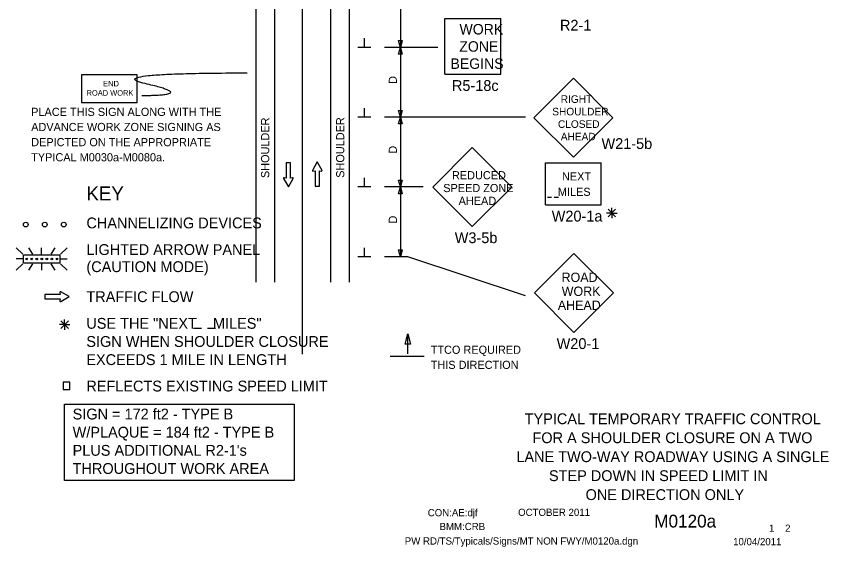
# Model space of a CAD drawing. Extents: x 16737 to 18470, y 7218 to 8193.
# Drawn here: x 16737 to 17435, y 7218 to 7674 of the extents above; entities that cross this region are included whole.
import ezdxf

# ---------------------------------------------------------------- set-up
doc = ezdxf.new("R2010")
doc.units = 0
for name, color, linetype in [('BORDER', 7, 'Continuous'), ('BORDER_SIGNAL_WO', 7, 'Continuous'), ('MT_SCRATCH_LEVEL_E', 7, 'Continuous'), ('PAVT_EDGE_EX', 7, 'Continuous'), ('TRAFFIC_SIGNS_PR', 7, 'Continuous'), ('TYPICAL_TEXT_DIMEN_EX', 7, 'Continuous'), ('TYPICAL_TEXT_DIMEN_PR', 7, 'Continuous')]:
    doc.layers.add(name, color=color, linetype=linetype)

msp = doc.modelspace()

# ---------------------------------------------------------------- linework, layer by layer
at = {"layer": 'MT_SCRATCH_LEVEL_E'}
for p, q in [((16972.86, 7548.17), (16969.12, 7548.17)), ((16969.12, 7548.17), (16969.12, 7534.91)), ((16972.86, 7548.17), (16969.12, 7548.17)), ((16969.12, 7548.17), (16969.12, 7534.91)), ((16972.86, 7534.91), (16972.86, 7548.17)), ((16972.86, 7534.91), (16972.86, 7548.17)), ((16995.75, 7548.82), (16991.64, 7541.58)), ((16995.75, 7548.82), (16991.64, 7541.58)), ((16999.89, 7541.58), (16995.75, 7548.82)), ((16999.89, 7541.58), (16995.75, 7548.82)), ((16992.12, 7540.9), (16993.9, 7541.21)), ((16992.12, 7540.9), (16993.9, 7541.21)), ((16993.9, 7541.21), (16993.9, 7527.96)), ((16993.9, 7541.21), (16993.9, 7527.96)), ((16997.64, 7527.96), (16997.64, 7541.21)), ((16997.64, 7541.21), (16999.42, 7540.9)), ((16997.64, 7527.96), (16997.64, 7541.21)), ((16997.64, 7541.21), (16999.42, 7540.9)), ((16966.86, 7534.54), (16971.01, 7527.3)), ((16966.86, 7534.54), (16971.01, 7527.3)), ((16969.12, 7534.91), (16967.34, 7535.22)), ((16969.12, 7534.91), (16967.34, 7535.22)), ((16971.01, 7527.3), (16975.12, 7534.54)), ((16971.01, 7527.3), (16975.12, 7534.54)), ((16974.64, 7535.22), (16972.86, 7534.91)), ((16974.64, 7535.22), (16972.86, 7534.91)), ((16993.9, 7527.96), (16997.64, 7527.96)), ((16993.9, 7527.96), (16997.64, 7527.96)), ((16775.11, 7434.93), (16761.85, 7434.93)), ((16761.85, 7434.93), (16761.85, 7431.19)), ((16775.11, 7434.93), (16761.85, 7434.93)), ((16761.85, 7434.93), (16761.85, 7431.19)), ((16761.85, 7431.19), (16775.11, 7431.19)), ((16761.85, 7431.19), (16775.11, 7431.19)), ((16774.79, 7436.71), (16775.11, 7434.93)), ((16774.79, 7436.71), (16775.11, 7434.93)), ((16775.11, 7431.19), (16774.79, 7429.41)), ((16775.11, 7431.19), (16774.79, 7429.41)), ((16782.72, 7433.08), (16775.48, 7437.19)), ((16782.72, 7433.08), (16775.48, 7437.19)), ((16775.48, 7428.94), (16782.72, 7433.08)), ((16775.48, 7428.94), (16782.72, 7433.08))]:
    msp.add_line(p, q, dxfattribs=at)
for centre, start, end in [((16992.04, 7541.36), 150.42484, 279.96381), ((16992.04, 7541.36), 150.42484, 279.96381), ((16999.48, 7541.36), 260.03619, 29.77312), ((16999.48, 7541.36), 260.03619, 29.77312), ((16967.27, 7534.76), 80.03619, 209.77312), ((16967.27, 7534.76), 80.03619, 209.77312), ((16974.71, 7534.76), 330.42484, 99.96381), ((16974.71, 7534.76), 330.42484, 99.96381), ((16775.25, 7436.79), 60.42484, 189.96381), ((16775.25, 7436.79), 60.42484, 189.96381), ((16775.25, 7429.34), 170.03619, 299.77312), ((16775.25, 7429.34), 170.03619, 299.77312)]:
    msp.add_arc(centre, 0.463, start, end, dxfattribs=at)
at = {"layer": 'PAVT_EDGE_EX'}
for p, q in [((16943.15, 8180.56), (16943.15, 7445.4)), ((16959.15, 8180.56), (16959.15, 7445.4)), ((16983.15, 7383.56), (16983.15, 8180.56)), ((17007.15, 8180.56), (17007.15, 7445.4)), ((17023.15, 8180.56), (17023.15, 7445.4))]:
    msp.add_line(p, q, dxfattribs=at)
for points in [[(16983.15, 7645.4), (16983.15, 7670.4)], [(16983.15, 7545.4), (16983.15, 7570.4)], [(16983.15, 7466.96), (16983.15, 7491.96)]]:
    msp.add_lwpolyline(points, dxfattribs=at)
at = {"layer": 'TRAFFIC_SIGNS_PR'}
for p, q in [((17105.46, 7624.13), (17105.46, 7672.13)), ((17105.46, 7672.13), (17153.46, 7672.13)), ((17153.46, 7624.13), (17153.46, 7672.13)), ((17105.46, 7624.13), (17153.46, 7624.13)), ((17215.73, 7620.81), (17181.79, 7586.87)), ((17249.67, 7586.87), (17215.73, 7620.81)), ((17181.79, 7586.87), (17215.73, 7552.93)), ((17215.73, 7552.93), (17249.67, 7586.87)), ((17128.94, 7561.2), (17095, 7527.26)), ((17162.88, 7527.26), (17128.94, 7561.2)), ((17191.73, 7511.93), (17191.73, 7547.93)), ((17191.73, 7547.93), (17239.73, 7547.93)), ((17239.73, 7511.93), (17239.73, 7547.93)), ((17095, 7527.26), (17128.94, 7493.32)), ((17128.94, 7493.32), (17162.88, 7527.26)), ((17193.58, 7518.53), (17197.08, 7518.53)), ((17199.38, 7518.53), (17202.88, 7518.53)), ((17191.73, 7511.93), (17239.73, 7511.93)), ((16737.3, 7475.13), (16742.94, 7469.49)), ((16751.48, 7469.49), (16748.22, 7475.13)), ((16759.11, 7469.49), (16759.11, 7475.13)), ((16767.38, 7469.49), (16770.64, 7475.13)), ((16775.28, 7469.49), (16780.92, 7475.13)), ((17216.18, 7470.21), (17182.24, 7436.27)), ((17250.12, 7436.27), (17216.18, 7470.21)), ((16742.94, 7465.43), (16737.3, 7465.43)), ((16737.3, 7455.73), (16742.94, 7461.36)), ((16746.22, 7465.43), (16746.22, 7465.43)), ((16748.17, 7455.72), (16751.43, 7461.36)), ((16750.57, 7465.43), (16750.57, 7465.43)), ((16754.91, 7465.43), (16754.91, 7465.43)), ((16759.11, 7461.36), (16759.11, 7455.72)), ((16759.26, 7465.43), (16759.26, 7465.43)), ((16763.61, 7465.43), (16763.61, 7465.43)), ((16770.69, 7455.72), (16767.43, 7461.36)), ((16767.96, 7465.43), (16767.96, 7465.43)), ((16772.3, 7465.43), (16772.3, 7465.43)), ((16775.28, 7465.43), (16780.92, 7465.43)), ((16775.28, 7461.36), (16780.92, 7455.72)), ((17182.24, 7436.27), (17216.18, 7402.33)), ((17216.18, 7402.33), (17250.12, 7436.27))]:
    msp.add_line(p, q, dxfattribs=at)
for points in [[(16793.2, 7599.81), (16841.2, 7599.81), (16841.2, 7623.81), (16793.2, 7623.81)], [(16774.82, 7461.83), (16743.41, 7461.83), (16743.41, 7469.03), (16774.82, 7469.03)]]:
    msp.add_lwpolyline(points, close=True, dxfattribs=at)
for centre, radius in [((16745.51, 7495.01), 2), ((16761.81, 7495.01), 2), ((16778.11, 7495.01), 2), ((16746.26, 7465.43), 0.758), ((16750.56, 7465.43), 0.758), ((16754.91, 7465.43), 0.758), ((16759.26, 7465.43), 0.758), ((16763.61, 7465.43), 0.758), ((16767.95, 7465.43), 0.758), ((16772.3, 7465.43), 0.758)]:
    msp.add_circle(centre, radius, dxfattribs=at)
msp.add_open_spline([(16845.07, 7605.98), (16892.31, 7605.98), (16807.28, 7625.33), (16935.57, 7625.33)], degree=2, dxfattribs=at)
at = {"layer": 'TYPICAL_TEXT_DIMEN_EX'}
msp.add_lwpolyline([(16777.65, 7353.39), (16783.25, 7353.39), (16783.25, 7359.56), (16777.65, 7359.56)], close=True, dxfattribs=at)
at = {"layer": 'TYPICAL_TEXT_DIMEN_PR'}
for p, q in [((17067.15, 7707.3), (17067.15, 7647.3)), ((17036.27, 7647.3), (17036.27, 7655.08)), ((17067.15, 7647.3), (17065.58, 7653.16)), ((17065.58, 7653.16), (17067.15, 7653.16)), ((17067.15, 7653.16), (17068.73, 7653.16)), ((17068.73, 7653.16), (17067.15, 7647.3)), ((17041.89, 7647.3), (17030.64, 7647.3)), ((17099.21, 7647.3), (17053.58, 7647.3)), ((17065.58, 7641.44), (17067.15, 7647.3)), ((17067.15, 7641.44), (17065.58, 7641.44)), ((17067.15, 7647.3), (17068.73, 7641.44)), ((17067.15, 7647.3), (17067.15, 7587.36)), ((17068.73, 7641.44), (17067.15, 7641.44)), ((17036.27, 7587.3), (17036.27, 7595.08)), ((17067.15, 7587.3), (17065.58, 7593.16)), ((17065.58, 7593.16), (17067.15, 7593.16)), ((17067.15, 7593.16), (17068.73, 7593.16)), ((17068.73, 7593.16), (17067.15, 7587.3)), ((17041.89, 7587.3), (17030.64, 7587.3)), ((17174.64, 7587.3), (17053.58, 7587.3)), ((17065.58, 7581.44), (17067.15, 7587.3)), ((17067.15, 7587.3), (17068.73, 7581.44)), ((17067.15, 7587.3), (17067.15, 7527.3)), ((17067.15, 7581.44), (17065.58, 7581.44)), ((17068.73, 7581.44), (17067.15, 7581.44)), ((17036.27, 7527.3), (17036.27, 7535.08)), ((17067.15, 7527.3), (17065.58, 7533.16)), ((17065.58, 7533.16), (17067.15, 7533.16)), ((17067.15, 7533.16), (17068.73, 7533.16)), ((17068.73, 7533.16), (17067.15, 7527.3)), ((17041.89, 7527.3), (17030.64, 7527.3)), ((17086.64, 7527.3), (17053.58, 7527.3)), ((17065.58, 7521.44), (17067.15, 7527.3)), ((17067.15, 7527.3), (17068.73, 7521.44)), ((17067.15, 7527.3), (17067.15, 7467.3)), ((17067.15, 7521.44), (17065.58, 7521.44)), ((17068.73, 7521.44), (17067.15, 7521.44)), ((17245.59, 7508.11), (17251.97, 7501.74)), ((17251.97, 7508.11), (17245.59, 7501.74)), ((17248.78, 7504.92), (17248.78, 7509.38)), ((17248.78, 7504.92), (17244.25, 7504.92)), ((17248.78, 7504.92), (17251.97, 7504.92)), ((17248.78, 7504.92), (17253.26, 7504.92)), ((17248.78, 7504.92), (17248.78, 7500.42)), ((17036.27, 7467.3), (17036.27, 7475.08)), ((17067.15, 7467.3), (17065.58, 7473.16)), ((17065.58, 7473.16), (17067.15, 7473.16)), ((17067.15, 7473.16), (17068.73, 7473.16)), ((17068.73, 7473.16), (17067.15, 7467.3)), ((17041.89, 7467.3), (17030.64, 7467.3)), ((17073.64, 7467.3), (17053.58, 7467.3)), ((17174.69, 7433.62), (17073.64, 7467.3)), ((16782.06, 7412.18), (16775.68, 7405.8)), ((16775.69, 7412.18), (16782.06, 7405.8)), ((16778.87, 7408.99), (16778.87, 7413.45)), ((16778.87, 7408.99), (16774.34, 7408.99)), ((16778.87, 7408.99), (16782.06, 7408.99)), ((16778.87, 7408.99), (16783.35, 7408.99)), ((16778.87, 7408.99), (16778.87, 7404.49)), ((16889.48, 7405.99), (16896.48, 7405.99)), ((16901.43, 7405.83), (16908.43, 7405.83)), ((17071.22, 7392.34), (17073.58, 7401.13)), ((17073.58, 7384.01), (17073.58, 7401.13)), ((17073.58, 7401.13), (17075.93, 7392.34)), ((17073.58, 7392.34), (17071.22, 7392.34)), ((17075.93, 7392.34), (17073.58, 7392.34)), ((17087.75, 7381.51), (17058.31, 7381.51))]:
    msp.add_line(p, q, dxfattribs=at)
msp.add_lwpolyline([(16778.8, 7340.64), (16976.08, 7340.64), (16976.08, 7275.1), (16778.8, 7275.1)], close=True, dxfattribs=at)

# ---------------------------------------------------------------- texts
at = {"layer": 'BORDER'}
for s, p in [('TYPICAL TEMPORARY TRAFFIC CONTROL', (17173.94, 7323.44)), ('FOR A SHOULDER CLOSURE ON A TWO', (17180.63, 7307.14)), ('LANE TWO-WAY ROADWAY USING A SINGLE', (17166.79, 7290.84)), ('STEP DOWN IN SPEED LIMIT IN', (17194.78, 7274.54)), ('ONE DIRECTION ONLY', (17226.22, 7258.24))]:
    msp.add_text(s, height=9.3, dxfattribs=at).set_placement(p)
at = {"layer": 'BORDER_SIGNAL_WO'}
for s, height, p in [('CON:AE:djf', 6.2, (17090.69, 7244.31)), ('    OCTOBER 2011    ', 6.2, (17159.08, 7244.59)), ('    M0120a    ', 11, (17268.86, 7234.63)), ('BMM:CRB   ', 6.2, (17100.81, 7232.42)), (' 1    2 ', 6.2, (17381.45, 7230.95)), ('PW RD/TS/Typicals/Signs/MT NON FWY/M0120a.dgn     ', 6.2, (17070.98, 7219.96)), ('10/04/2011    ', 6.2, (17352.93, 7219.38))]:
    msp.add_text(s, height=height, dxfattribs=at).set_placement(p)
at = {"layer": 'TRAFFIC_SIGNS_PR'}
for s, height, p in [('R2-1', 9.3, (17204.23, 7661.66)), ('WORK', 9.021, (17117.96, 7658.34)), ('ZONE', 9.021, (17117.81, 7643.57)), ('BEGINS', 9.021, (17110.22, 7628.81)), ('END', 4.789, (16811.95, 7613.72)), ('R5-18c', 9.3, (17111.47, 7609.83)), ('ROAD WORK', 4.789, (16797.71, 7605.74)), ('RIGHT', 6.5, (17204.88, 7599.6)), ('PLACE THIS SIGN ALONG WITH THE', 7, (16750.14, 7588.35)), ('SHOULDER', 6.5, (17197.61, 7588.85)), ('CLOSED', 6.5, (17202.5, 7578.1)), ('ADVANCE WORK ZONE SIGNING AS', 7, (16750.14, 7575.35)), ('AHEAD', 6.5, (17204.95, 7567.35)), ('DEPICTED ON THE APPROPRIATE', 7, (16750.14, 7562.35)), ('W21-5b', 9.3, (17239.91, 7559.94)), ('TYPICAL M0030a-M0080a.', 7, (16750.14, 7549.35)), ('REDUCED', 7, (17111.51, 7533.9)), ('NEXT', 7, (17205.98, 7532.93)), ('SPEED ZONE', 7, (17104, 7522.9)), ('   MILES', 7, (17194.64, 7519.63)), ('AHEAD', 7, (17117.2, 7511.9)), ('W20-1a', 9.3, (17197.15, 7497.63)), ('W3-5b', 9.3, (17113.88, 7479.02)), ('ROAD', 8, (17205.61, 7445.69)), ('WORK', 8, (17205.74, 7433.69)), ('AHEAD', 8, (17202.38, 7421.69)), ('W20-1', 9.3, (17201.39, 7388.03))]:
    msp.add_text(s, height=height, dxfattribs=at).set_placement(p)
at = {"layer": 'TYPICAL_TEXT_DIMEN_EX'}
for s, height, p in [('KEY', 12, (16797.56, 7515.74)), ('CHANNELIZING DEVICES', 9.3, (16797.56, 7491.74)), ('LIGHTED ARROW PANEL', 9.3, (16797.56, 7468.85)), ('(CAUTION MODE)', 9.3, (16797.56, 7454.15)), ('TRAFFIC FLOW', 9.3, (16797.56, 7428.35)), ('USE THE "NEXT    MILES"', 9.3, (16797.48, 7405.46)), ('SIGN WHEN SHOULDER CLOSURE', 9.3, (16797.48, 7389.86)), ('EXCEEDS 1 MILE IN LENGTH', 9.3, (16797.48, 7374.26)), ('REFLECTS EXISTING SPEED LIMIT', 9.3, (16797.48, 7351.55))]:
    msp.add_text(s, height=height, dxfattribs=at).set_placement(p)
at = {"layer": 'TYPICAL_TEXT_DIMEN_PR'}
for s, p in [('D', (17064.19, 7615.92)), ('SHOULDER', (16954.55, 7534.96)), ('SHOULDER', (17019, 7535.21)), ('D', (17064.19, 7555.92)), ('D', (17064.19, 7495.92))]:
    msp.add_text(s, height=7, rotation=90, dxfattribs=at).set_placement(p)
for s, height, p in [('TTCO REQUIRED', 7, (17093.27, 7383.93)), ('THIS DIRECTION', 7, (17093.27, 7370.93)), ('SIGN = 172 ft2 - TYPE B', 9.3, (16785.73, 7327.5)), ('W/PLAQUE = 184 ft2 - TYPE B', 9.3, (16785.73, 7311.9)), ("PLUS ADDITIONAL R2-1's", 9.3, (16785.73, 7296.3)), ('THROUGHOUT WORK AREA', 9.3, (16785.73, 7280.7))]:
    msp.add_text(s, height=height, dxfattribs=at).set_placement(p)

doc.saveas('drawing.dxf')
